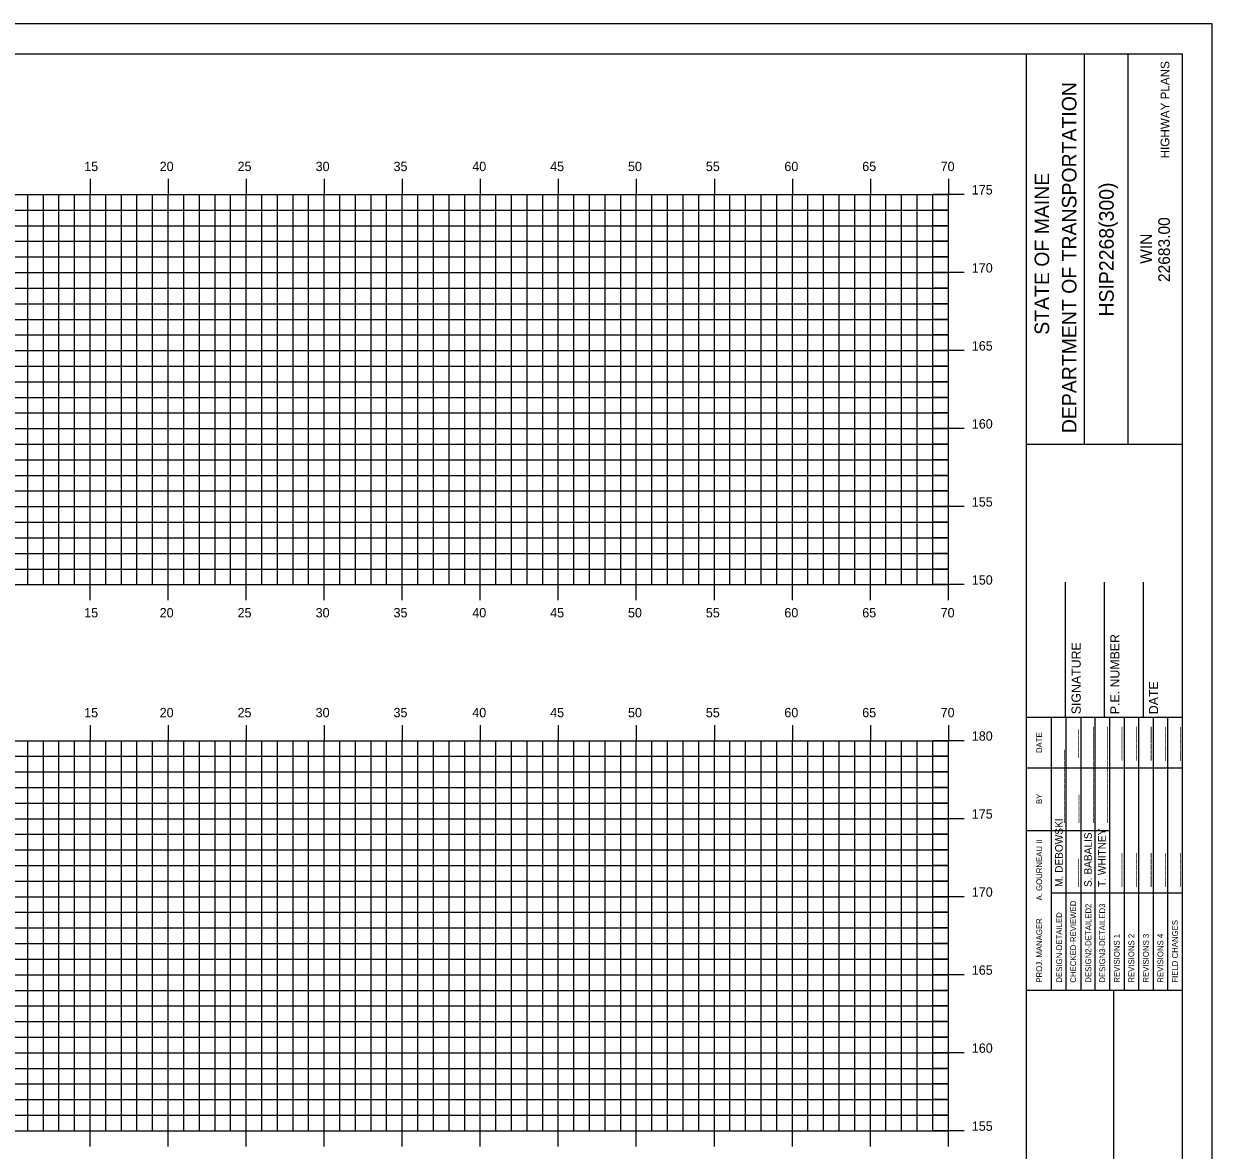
# Model space of a CAD drawing. Extents: x 1668473 to 1668643, y 337823 to 337933.
# Drawn here: x 1668566.5 to 1668642.7, y 337861.2 to 337933.4 of the extents above; entities that cross this region are included whole.
import ezdxf

# ---------------------------------------------------------------- set-up
doc = ezdxf.new("R2010")
doc.units = 0
for name, color, linetype in [('BORDER', 7, 'Continuous'), ('H_V ANNOTATION', 7, 'Continuous'), ('HIGHWAY_TITLE', 7, 'Continuous'), ('MAJOR', 7, 'Continuous'), ('MINOR', 7, 'Continuous'), ('PLOT BOUNDARY', 7, 'Continuous')]:
    doc.layers.add(name, color=color, linetype=linetype)

msp = doc.modelspace()

# ---------------------------------------------------------------- linework, layer by layer
at = {"layer": 'BORDER'}
for p, q in [((1668640.786, 337931.453), (1668480.786, 337931.453)), ((1668630.786, 337826.453), (1668630.786, 337931.456)), ((1668634.514, 337906.451), (1668634.514, 337931.451)), ((1668637.309, 337906.451), (1668637.309, 337931.451)), ((1668640.786, 337826.453), (1668640.786, 337931.453)), ((1668630.787, 337906.448), (1668640.786, 337906.448)), ((1668633.286, 337888.956), (1668633.286, 337897.604)), ((1668635.786, 337888.956), (1668635.786, 337897.604)), ((1668638.286, 337888.956), (1668638.286, 337897.604)), ((1668630.786, 337888.956), (1668640.786, 337888.956)), ((1668630.786, 337871.456), (1668640.786, 337871.456)), ((1668636.377, 337836.456), (1668636.377, 337871.456))]:
    msp.add_line(p, q, dxfattribs=at)
for points in [[(1668632.4, 337885.706), (1668632.4, 337888.956)], [(1668633.333, 337871.459), (1668633.333, 337888.956)], [(1668634.265, 337888.956), (1668634.265, 337871.459)], [(1668635.196, 337871.459), (1668635.196, 337888.956)], [(1668636.128, 337871.459), (1668636.128, 337888.956)], [(1668637.06, 337871.459), (1668637.06, 337888.956)], [(1668637.991, 337871.459), (1668637.991, 337888.956)], [(1668638.923, 337871.459), (1668638.923, 337888.956)], [(1668639.855, 337871.459), (1668639.855, 337888.956)], [(1668632.401, 337871.459), (1668632.401, 337888.25)], [(1668630.786, 337885.706), (1668640.786, 337885.706)], [(1668630.786, 337881.706), (1668632.401, 337881.706)], [(1668632.4, 337881.706), (1668636.127, 337881.706)], [(1668632.4, 337877.706), (1668640.786, 337877.706)]]:
    msp.add_lwpolyline(points, dxfattribs=at)
at = {"layer": 'MAJOR'}
for p, q in [((1668570.785, 337923.455), (1668570.785, 337922.453)), ((1668575.785, 337923.455), (1668575.785, 337922.453)), ((1668580.785, 337923.455), (1668580.785, 337922.453)), ((1668585.785, 337923.455), (1668585.785, 337922.453)), ((1668590.785, 337923.455), (1668590.785, 337922.453)), ((1668595.785, 337923.455), (1668595.785, 337922.453)), ((1668600.785, 337923.455), (1668600.785, 337922.453)), ((1668605.785, 337923.455), (1668605.785, 337922.453)), ((1668610.785, 337923.455), (1668610.785, 337922.453)), ((1668615.785, 337923.455), (1668615.785, 337922.453)), ((1668620.785, 337923.455), (1668620.785, 337922.453)), ((1668625.785, 337923.455), (1668625.785, 337922.453)), ((1668485.785, 337922.453), (1668625.785, 337922.453)), ((1668485.785, 337922.453), (1668625.785, 337922.453)), ((1668570.785, 337897.453), (1668570.785, 337922.453)), ((1668575.785, 337897.453), (1668575.785, 337922.453)), ((1668580.785, 337897.453), (1668580.785, 337922.453)), ((1668585.785, 337897.453), (1668585.785, 337922.453)), ((1668590.785, 337897.453), (1668590.785, 337922.453)), ((1668595.785, 337897.453), (1668595.785, 337922.453)), ((1668600.785, 337897.453), (1668600.785, 337922.453)), ((1668605.785, 337897.453), (1668605.785, 337922.453)), ((1668610.785, 337897.453), (1668610.785, 337922.453)), ((1668615.785, 337897.453), (1668615.785, 337922.453)), ((1668620.785, 337897.453), (1668620.785, 337922.453)), ((1668626.787, 337922.453), (1668624.783, 337922.453)), ((1668625.785, 337897.453), (1668625.785, 337922.453)), ((1668625.785, 337897.453), (1668625.785, 337922.453)), ((1668485.785, 337917.453), (1668625.785, 337917.453)), ((1668626.787, 337917.453), (1668624.783, 337917.453)), ((1668485.785, 337912.453), (1668625.785, 337912.453)), ((1668626.787, 337912.453), (1668624.783, 337912.453)), ((1668485.785, 337907.453), (1668625.785, 337907.453)), ((1668626.787, 337907.453), (1668624.783, 337907.453)), ((1668485.785, 337902.453), (1668625.785, 337902.453)), ((1668626.787, 337902.453), (1668624.783, 337902.453)), ((1668485.785, 337897.453), (1668625.785, 337897.453)), ((1668485.785, 337897.453), (1668625.785, 337897.453)), ((1668570.785, 337896.451), (1668570.785, 337897.453)), ((1668575.785, 337896.451), (1668575.785, 337897.453)), ((1668580.785, 337896.451), (1668580.785, 337897.453)), ((1668585.785, 337896.451), (1668585.785, 337897.453)), ((1668590.785, 337896.451), (1668590.785, 337897.453)), ((1668595.785, 337896.451), (1668595.785, 337897.453)), ((1668600.785, 337896.451), (1668600.785, 337897.453)), ((1668605.785, 337896.451), (1668605.785, 337897.453)), ((1668610.785, 337896.451), (1668610.785, 337897.453)), ((1668615.785, 337896.451), (1668615.785, 337897.453)), ((1668620.785, 337896.451), (1668620.785, 337897.453)), ((1668626.787, 337897.453), (1668624.783, 337897.453)), ((1668625.785, 337896.451), (1668625.785, 337897.453)), ((1668570.785, 337888.455), (1668570.785, 337887.453)), ((1668575.785, 337888.455), (1668575.785, 337887.453)), ((1668580.785, 337888.455), (1668580.785, 337887.453)), ((1668585.785, 337888.455), (1668585.785, 337887.453)), ((1668590.785, 337888.455), (1668590.785, 337887.453)), ((1668595.785, 337888.455), (1668595.785, 337887.453)), ((1668600.785, 337888.455), (1668600.785, 337887.453)), ((1668605.785, 337888.455), (1668605.785, 337887.453)), ((1668610.785, 337888.455), (1668610.785, 337887.453)), ((1668615.785, 337888.455), (1668615.785, 337887.453)), ((1668620.785, 337888.455), (1668620.785, 337887.453)), ((1668625.785, 337888.455), (1668625.785, 337887.453)), ((1668485.785, 337887.453), (1668625.785, 337887.453)), ((1668485.785, 337887.453), (1668625.785, 337887.453)), ((1668570.785, 337862.453), (1668570.785, 337887.453)), ((1668575.785, 337862.453), (1668575.785, 337887.453)), ((1668580.785, 337862.453), (1668580.785, 337887.453)), ((1668585.785, 337862.453), (1668585.785, 337887.453)), ((1668590.785, 337862.453), (1668590.785, 337887.453)), ((1668595.785, 337862.453), (1668595.785, 337887.453)), ((1668600.785, 337862.453), (1668600.785, 337887.453)), ((1668605.785, 337862.453), (1668605.785, 337887.453)), ((1668610.785, 337862.453), (1668610.785, 337887.453)), ((1668615.785, 337862.453), (1668615.785, 337887.453)), ((1668620.785, 337862.453), (1668620.785, 337887.453)), ((1668626.787, 337887.453), (1668624.783, 337887.453)), ((1668625.785, 337862.453), (1668625.785, 337887.453)), ((1668625.785, 337862.453), (1668625.785, 337887.453)), ((1668485.785, 337882.453), (1668625.785, 337882.453)), ((1668626.787, 337882.453), (1668624.783, 337882.453)), ((1668485.785, 337877.453), (1668625.785, 337877.453)), ((1668626.787, 337877.453), (1668624.783, 337877.453)), ((1668485.785, 337872.453), (1668625.785, 337872.453)), ((1668626.787, 337872.453), (1668624.783, 337872.453)), ((1668485.785, 337867.453), (1668625.785, 337867.453)), ((1668626.787, 337867.453), (1668624.783, 337867.453)), ((1668485.785, 337862.453), (1668625.785, 337862.453)), ((1668485.785, 337862.453), (1668625.785, 337862.453)), ((1668570.785, 337861.451), (1668570.785, 337862.453)), ((1668575.785, 337861.451), (1668575.785, 337862.453)), ((1668580.785, 337861.451), (1668580.785, 337862.453)), ((1668585.785, 337861.451), (1668585.785, 337862.453)), ((1668590.785, 337861.451), (1668590.785, 337862.453)), ((1668595.785, 337861.451), (1668595.785, 337862.453)), ((1668600.785, 337861.451), (1668600.785, 337862.453)), ((1668605.785, 337861.451), (1668605.785, 337862.453)), ((1668610.785, 337861.451), (1668610.785, 337862.453)), ((1668615.785, 337861.451), (1668615.785, 337862.453)), ((1668620.785, 337861.451), (1668620.785, 337862.453)), ((1668626.787, 337862.453), (1668624.783, 337862.453)), ((1668625.785, 337861.451), (1668625.785, 337862.453))]:
    msp.add_line(p, q, dxfattribs=at)
at = {"layer": 'MINOR'}
for p, q in [((1668566.785, 337897.453), (1668566.785, 337922.453)), ((1668567.785, 337897.453), (1668567.785, 337922.453)), ((1668568.785, 337897.453), (1668568.785, 337922.453)), ((1668569.785, 337897.453), (1668569.785, 337922.453)), ((1668571.785, 337897.453), (1668571.785, 337922.453)), ((1668572.785, 337897.453), (1668572.785, 337922.453)), ((1668573.785, 337897.453), (1668573.785, 337922.453)), ((1668574.785, 337897.453), (1668574.785, 337922.453)), ((1668576.785, 337897.453), (1668576.785, 337922.453)), ((1668577.785, 337897.453), (1668577.785, 337922.453)), ((1668578.785, 337897.453), (1668578.785, 337922.453)), ((1668579.785, 337897.453), (1668579.785, 337922.453)), ((1668581.785, 337897.453), (1668581.785, 337922.453)), ((1668582.785, 337897.453), (1668582.785, 337922.453)), ((1668583.785, 337897.453), (1668583.785, 337922.453)), ((1668584.785, 337897.453), (1668584.785, 337922.453)), ((1668586.785, 337897.453), (1668586.785, 337922.453)), ((1668587.785, 337897.453), (1668587.785, 337922.453)), ((1668588.785, 337897.453), (1668588.785, 337922.453)), ((1668589.785, 337897.453), (1668589.785, 337922.453)), ((1668591.785, 337897.453), (1668591.785, 337922.453)), ((1668592.785, 337897.453), (1668592.785, 337922.453)), ((1668593.785, 337897.453), (1668593.785, 337922.453)), ((1668594.785, 337897.453), (1668594.785, 337922.453)), ((1668596.785, 337897.453), (1668596.785, 337922.453)), ((1668597.785, 337897.453), (1668597.785, 337922.453)), ((1668598.785, 337897.453), (1668598.785, 337922.453)), ((1668599.785, 337897.453), (1668599.785, 337922.453)), ((1668601.785, 337897.453), (1668601.785, 337922.453)), ((1668602.785, 337897.453), (1668602.785, 337922.453)), ((1668603.785, 337897.453), (1668603.785, 337922.453)), ((1668604.785, 337897.453), (1668604.785, 337922.453)), ((1668606.785, 337897.453), (1668606.785, 337922.453)), ((1668607.785, 337897.453), (1668607.785, 337922.453)), ((1668608.785, 337897.453), (1668608.785, 337922.453)), ((1668609.785, 337897.453), (1668609.785, 337922.453)), ((1668611.785, 337897.453), (1668611.785, 337922.453)), ((1668612.785, 337897.453), (1668612.785, 337922.453)), ((1668613.785, 337897.453), (1668613.785, 337922.453)), ((1668614.785, 337897.453), (1668614.785, 337922.453)), ((1668616.785, 337897.453), (1668616.785, 337922.453)), ((1668617.785, 337897.453), (1668617.785, 337922.453)), ((1668618.785, 337897.453), (1668618.785, 337922.453)), ((1668619.785, 337897.453), (1668619.785, 337922.453)), ((1668621.785, 337897.453), (1668621.785, 337922.453)), ((1668622.785, 337897.453), (1668622.785, 337922.453)), ((1668623.785, 337897.453), (1668623.785, 337922.453)), ((1668624.785, 337897.453), (1668624.785, 337922.453)), ((1668485.785, 337921.453), (1668625.785, 337921.453)), ((1668625.785, 337921.453), (1668624.783, 337921.453)), ((1668485.785, 337920.453), (1668625.785, 337920.453)), ((1668625.785, 337920.453), (1668624.783, 337920.453)), ((1668485.785, 337919.453), (1668625.785, 337919.453)), ((1668625.785, 337919.453), (1668624.783, 337919.453)), ((1668485.785, 337918.453), (1668625.785, 337918.453)), ((1668625.785, 337918.453), (1668624.783, 337918.453)), ((1668485.785, 337916.453), (1668625.785, 337916.453)), ((1668625.785, 337916.453), (1668624.783, 337916.453)), ((1668485.785, 337915.453), (1668625.785, 337915.453)), ((1668625.785, 337915.453), (1668624.783, 337915.453)), ((1668485.785, 337914.453), (1668625.785, 337914.453)), ((1668625.785, 337914.453), (1668624.783, 337914.453)), ((1668485.785, 337913.453), (1668625.785, 337913.453)), ((1668625.785, 337913.453), (1668624.783, 337913.453)), ((1668485.785, 337911.453), (1668625.785, 337911.453)), ((1668625.785, 337911.453), (1668624.783, 337911.453)), ((1668485.785, 337910.453), (1668625.785, 337910.453)), ((1668625.785, 337910.453), (1668624.783, 337910.453)), ((1668485.785, 337909.453), (1668625.785, 337909.453)), ((1668625.785, 337909.453), (1668624.783, 337909.453)), ((1668485.785, 337908.453), (1668625.785, 337908.453)), ((1668625.785, 337908.453), (1668624.783, 337908.453)), ((1668485.785, 337906.453), (1668625.785, 337906.453)), ((1668625.785, 337906.453), (1668624.783, 337906.453)), ((1668485.785, 337905.453), (1668625.785, 337905.453)), ((1668625.785, 337905.453), (1668624.783, 337905.453)), ((1668485.785, 337904.453), (1668625.785, 337904.453)), ((1668625.785, 337904.453), (1668624.783, 337904.453)), ((1668485.785, 337903.453), (1668625.785, 337903.453)), ((1668625.785, 337903.453), (1668624.783, 337903.453)), ((1668485.785, 337901.453), (1668625.785, 337901.453)), ((1668625.785, 337901.453), (1668624.783, 337901.453)), ((1668485.785, 337900.453), (1668625.785, 337900.453)), ((1668625.785, 337900.453), (1668624.783, 337900.453)), ((1668485.785, 337899.453), (1668625.785, 337899.453)), ((1668625.785, 337899.453), (1668624.783, 337899.453)), ((1668485.785, 337898.453), (1668625.785, 337898.453)), ((1668625.785, 337898.453), (1668624.783, 337898.453)), ((1668566.785, 337862.453), (1668566.785, 337887.453)), ((1668567.785, 337862.453), (1668567.785, 337887.453)), ((1668568.785, 337862.453), (1668568.785, 337887.453)), ((1668569.785, 337862.453), (1668569.785, 337887.453)), ((1668571.785, 337862.453), (1668571.785, 337887.453)), ((1668572.785, 337862.453), (1668572.785, 337887.453)), ((1668573.785, 337862.453), (1668573.785, 337887.453)), ((1668574.785, 337862.453), (1668574.785, 337887.453)), ((1668576.785, 337862.453), (1668576.785, 337887.453)), ((1668577.785, 337862.453), (1668577.785, 337887.453)), ((1668578.785, 337862.453), (1668578.785, 337887.453)), ((1668579.785, 337862.453), (1668579.785, 337887.453)), ((1668581.785, 337862.453), (1668581.785, 337887.453)), ((1668582.785, 337862.453), (1668582.785, 337887.453)), ((1668583.785, 337862.453), (1668583.785, 337887.453)), ((1668584.785, 337862.453), (1668584.785, 337887.453)), ((1668586.785, 337862.453), (1668586.785, 337887.453)), ((1668587.785, 337862.453), (1668587.785, 337887.453)), ((1668588.785, 337862.453), (1668588.785, 337887.453)), ((1668589.785, 337862.453), (1668589.785, 337887.453)), ((1668591.785, 337862.453), (1668591.785, 337887.453)), ((1668592.785, 337862.453), (1668592.785, 337887.453)), ((1668593.785, 337862.453), (1668593.785, 337887.453)), ((1668594.785, 337862.453), (1668594.785, 337887.453)), ((1668596.785, 337862.453), (1668596.785, 337887.453)), ((1668597.785, 337862.453), (1668597.785, 337887.453)), ((1668598.785, 337862.453), (1668598.785, 337887.453)), ((1668599.785, 337862.453), (1668599.785, 337887.453)), ((1668601.785, 337862.453), (1668601.785, 337887.453)), ((1668602.785, 337862.453), (1668602.785, 337887.453)), ((1668603.785, 337862.453), (1668603.785, 337887.453)), ((1668604.785, 337862.453), (1668604.785, 337887.453)), ((1668606.785, 337862.453), (1668606.785, 337887.453)), ((1668607.785, 337862.453), (1668607.785, 337887.453)), ((1668608.785, 337862.453), (1668608.785, 337887.453)), ((1668609.785, 337862.453), (1668609.785, 337887.453)), ((1668611.785, 337862.453), (1668611.785, 337887.453)), ((1668612.785, 337862.453), (1668612.785, 337887.453)), ((1668613.785, 337862.453), (1668613.785, 337887.453)), ((1668614.785, 337862.453), (1668614.785, 337887.453)), ((1668616.785, 337862.453), (1668616.785, 337887.453)), ((1668617.785, 337862.453), (1668617.785, 337887.453)), ((1668618.785, 337862.453), (1668618.785, 337887.453)), ((1668619.785, 337862.453), (1668619.785, 337887.453)), ((1668621.785, 337862.453), (1668621.785, 337887.453)), ((1668622.785, 337862.453), (1668622.785, 337887.453)), ((1668623.785, 337862.453), (1668623.785, 337887.453)), ((1668624.785, 337862.453), (1668624.785, 337887.453)), ((1668485.785, 337886.453), (1668625.785, 337886.453)), ((1668625.785, 337886.453), (1668624.783, 337886.453)), ((1668485.785, 337885.453), (1668625.785, 337885.453)), ((1668625.785, 337885.453), (1668624.783, 337885.453)), ((1668485.785, 337884.453), (1668625.785, 337884.453)), ((1668625.785, 337884.453), (1668624.783, 337884.453)), ((1668485.785, 337883.453), (1668625.785, 337883.453)), ((1668625.785, 337883.453), (1668624.783, 337883.453)), ((1668485.785, 337881.453), (1668625.785, 337881.453)), ((1668625.785, 337881.453), (1668624.783, 337881.453)), ((1668485.785, 337880.453), (1668625.785, 337880.453)), ((1668625.785, 337880.453), (1668624.783, 337880.453)), ((1668485.785, 337879.453), (1668625.785, 337879.453)), ((1668625.785, 337879.453), (1668624.783, 337879.453)), ((1668485.785, 337878.453), (1668625.785, 337878.453)), ((1668625.785, 337878.453), (1668624.783, 337878.453)), ((1668485.785, 337876.453), (1668625.785, 337876.453)), ((1668625.785, 337876.453), (1668624.783, 337876.453)), ((1668485.785, 337875.453), (1668625.785, 337875.453)), ((1668625.785, 337875.453), (1668624.783, 337875.453)), ((1668485.785, 337874.453), (1668625.785, 337874.453)), ((1668625.785, 337874.453), (1668624.783, 337874.453)), ((1668485.785, 337873.453), (1668625.785, 337873.453)), ((1668625.785, 337873.453), (1668624.783, 337873.453)), ((1668485.785, 337871.453), (1668625.785, 337871.453)), ((1668625.785, 337871.453), (1668624.783, 337871.453)), ((1668485.785, 337870.453), (1668625.785, 337870.453)), ((1668625.785, 337870.453), (1668624.783, 337870.453)), ((1668485.785, 337869.453), (1668625.785, 337869.453)), ((1668625.785, 337869.453), (1668624.783, 337869.453)), ((1668485.785, 337868.453), (1668625.785, 337868.453)), ((1668625.785, 337868.453), (1668624.783, 337868.453)), ((1668485.785, 337866.453), (1668625.785, 337866.453)), ((1668625.785, 337866.453), (1668624.783, 337866.453)), ((1668485.785, 337865.453), (1668625.785, 337865.453)), ((1668625.785, 337865.453), (1668624.783, 337865.453)), ((1668485.785, 337864.453), (1668625.785, 337864.453)), ((1668625.785, 337864.453), (1668624.783, 337864.453)), ((1668485.785, 337863.453), (1668625.785, 337863.453)), ((1668625.785, 337863.453), (1668624.783, 337863.453))]:
    msp.add_line(p, q, dxfattribs=at)
at = {"layer": 'PLOT BOUNDARY'}
msp.add_lwpolyline([(1668472.692, 337823.394), (1668642.692, 337823.394), (1668642.692, 337933.394), (1668472.692, 337933.394)], close=True, dxfattribs=at)

# ---------------------------------------------------------------- texts
at = {"layer": 'BORDER'}
for s, height, p in [('DEPARTMENT OF TRANSPORTATION', 0.93176, (1668633.992, 337907.159)), ('STATE OF MAINE', 0.93176, (1668632.241, 337913.465)), ('HSIP2268(300)', 0.93176, (1668636.378, 337914.634)), ('22683.00', 0.7453, (1668639.981, 337916.84)), ('WIN', 0.7453, (1668638.822, 337918.011)), ('P.E. NUMBER', 0.59055, (1668636.746, 337889.149)), ('SIGNATURE', 0.5906, (1668634.266, 337889.149)), ('DATE', 0.5906, (1668639.227, 337889.149)), ('DATE', 0.3714, (1668631.79, 337886.662)), ('_____', 0.4845, (1668634.003, 337886.362)), ('______', 0.4845, (1668634.972, 337886.182)), ('______', 0.4845, (1668635.866, 337886.182)), ('______', 0.4845, (1668636.798, 337886.183)), ('______', 0.4845, (1668637.73, 337886.185)), ('______', 0.4845, (1668638.661, 337886.185)), ('______', 0.4845, (1668639.593, 337886.155)), ('______', 0.4845, (1668640.525, 337886.154)), ('_____________', 0.48455, (1668633.109, 337882.192)), ('____________', 0.48455, (1668634.972, 337882.192)), ('____________', 0.48455, (1668635.866, 337882.192)), ('BY', 0.3714, (1668631.79, 337883.392)), ('_____', 0.4845, (1668634.04, 337882.192)), ('M. DEBOWSKI', 0.48455, (1668633.109, 337878.08)), ('T. WHITNEY', 0.4845, (1668635.866, 337878.08)), ('A. GOURNEAU II', 0.37275, (1668631.79, 337877.213)), ('S. BABALIS', 0.4845, (1668634.972, 337878.08)), ('______', 0.4845, (1668636.798, 337878.08)), ('______', 0.4845, (1668637.73, 337878.08)), ('______', 0.4845, (1668638.661, 337878.08)), ('______', 0.4845, (1668639.593, 337878.08)), ('______', 0.4845, (1668640.525, 337878.08)), ('_____', 0.4845, (1668634.003, 337878.08)), ('CHECKED-REVIEWED', 0.37275, (1668633.967, 337871.945)), ('DESIGN-DETAILED', 0.37275, (1668633.072, 337871.945)), ('DESIGN2-DETAILED2', 0.37275, (1668634.936, 337871.945)), ('DESIGN3-DETAILED3', 0.37275, (1668635.83, 337871.945)), ('PROJ. MANAGER', 0.37275, (1668631.79, 337871.945)), ('FIELD CHANGES', 0.37275, (1668640.488, 337871.945)), ('REVISIONS 1', 0.37275, (1668636.762, 337871.945)), ('REVISIONS 2', 0.37275, (1668637.693, 337871.945)), ('REVISIONS 3', 0.37275, (1668638.625, 337871.945)), ('REVISIONS 4', 0.37275, (1668639.557, 337871.945))]:
    msp.add_text(s, height=height, rotation=90, dxfattribs=at).set_placement(p)
at = {"layer": 'H_V ANNOTATION'}
for s, p in [('15', (1668570.403, 337923.953)), ('20', (1668575.239, 337923.953)), ('25', (1668580.231, 337923.953)), ('30', (1668585.234, 337923.953)), ('35', (1668590.226, 337923.953)), ('40', (1668595.272, 337923.953)), ('45', (1668600.264, 337923.953)), ('50', (1668605.25, 337923.953)), ('55', (1668610.242, 337923.953)), ('60', (1668615.272, 337923.953)), ('65', (1668620.264, 337923.953)), ('70', (1668625.288, 337923.953)), ('175', (1668627.285, 337922.453)), ('170', (1668627.285, 337917.453)), ('165', (1668627.285, 337912.453)), ('160', (1668627.285, 337907.453)), ('155', (1668627.285, 337902.453)), ('150', (1668627.285, 337897.453)), ('15', (1668570.403, 337895.353)), ('20', (1668575.239, 337895.353)), ('25', (1668580.231, 337895.353)), ('30', (1668585.234, 337895.353)), ('35', (1668590.226, 337895.353)), ('40', (1668595.272, 337895.353)), ('45', (1668600.264, 337895.353)), ('50', (1668605.25, 337895.353)), ('55', (1668610.242, 337895.353)), ('60', (1668615.272, 337895.353)), ('65', (1668620.264, 337895.353)), ('70', (1668625.288, 337895.353)), ('15', (1668570.403, 337888.953)), ('20', (1668575.239, 337888.953)), ('25', (1668580.231, 337888.953)), ('30', (1668585.234, 337888.953)), ('35', (1668590.226, 337888.953)), ('40', (1668595.272, 337888.953)), ('45', (1668600.264, 337888.953)), ('50', (1668605.25, 337888.953)), ('55', (1668610.242, 337888.953)), ('60', (1668615.272, 337888.953)), ('65', (1668620.264, 337888.953)), ('70', (1668625.288, 337888.953)), ('180', (1668627.285, 337887.453)), ('175', (1668627.285, 337882.453)), ('170', (1668627.285, 337877.453)), ('165', (1668627.285, 337872.453)), ('160', (1668627.285, 337867.453)), ('155', (1668627.285, 337862.453))]:
    msp.add_text(s, height=0.6, dxfattribs=at).set_placement(p)
at = {"layer": 'HIGHWAY_TITLE'}
msp.add_text('HIGHWAY PLANS', height=0.55901, rotation=90, dxfattribs=at).set_placement((1668639.944, 337924.769))

doc.saveas('drawing.dxf')
